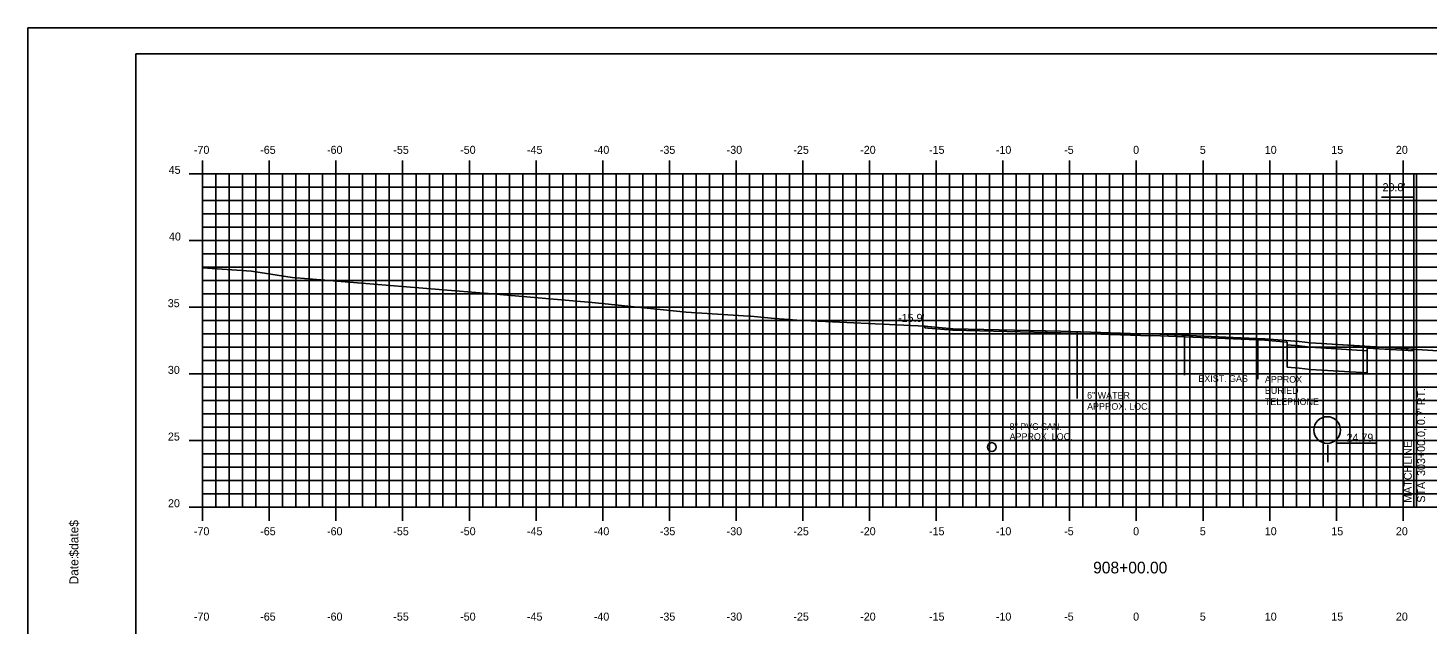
# Model space of a CAD drawing. Extents: x 1026131 to 1026301, y 394697 to 394807.
# Drawn here: x 1026131.3 to 1026236.1, y 394761.9 to 394806.5 of the extents above; entities that cross this region are included whole.
import ezdxf

# ---------------------------------------------------------------- set-up
doc = ezdxf.new("R2010")
doc.units = 0
for name, color, linetype in [('ANNOTATION', 7, 'Continuous'), ('BORDER', 7, 'Continuous'), ('D_Drainage_Culvert', 7, 'Continuous'), ('D_Drainage_Text', 7, 'Continuous'), ('D_Roadway_FinishedGrade', 7, 'Continuous'), ('D_Text_Monospaced', 7, 'Continuous'), ('D_Text_Standard', 7, 'Continuous'), ('H_V ANNOTATION', 7, 'Continuous'), ('MAJOR', 7, 'Continuous'), ('MINOR', 7, 'Continuous'), ('PLOT BOUNDARY', 7, 'Continuous'), ('S_Roadway_Centerline', 7, 'Continuous'), ('S_Utilities_UG_Gas_Line', 7, 'Continuous'), ('S_Utilities_UG_Sanitary_Sewer', 7, 'Continuous'), ('S_Utilities_UG_Water_Line', 7, 'Continuous')]:
    doc.layers.add(name, color=color, linetype=linetype)

msp = doc.modelspace()

# ---------------------------------------------------------------- linework, layer by layer
at = {"layer": 'ANNOTATION'}
for p, q in [((1026232.72, 394793.87), (1026235.14, 394793.87)), ((1026228.69, 394774), (1026228.69, 394775.3))]:
    msp.add_line(p, q, dxfattribs=at)
at = {"layer": 'BORDER'}
for p, q in [((1026299.34, 394804.61), (1026139.34, 394804.61)), ((1026139.34, 394804.61), (1026139.34, 394699.61))]:
    msp.add_line(p, q, dxfattribs=at)
at = {"layer": 'D_Drainage_Culvert'}
msp.add_circle((1026228.65, 394776.4), 1, dxfattribs=at)
at = {"layer": 'D_Drainage_Text'}
msp.add_lwpolyline([(1026229.34, 394775.42), (1026230.56, 394775.42), (1026232.4, 394775.42)], dxfattribs=at)
at = {"layer": 'D_Roadway_FinishedGrade'}
for p, q in [((1026235.14, 394770.61), (1026235.14, 394795.61)), ((1026198.48, 394784.06), (1026198.48, 394784.19)), ((1026225.65, 394781.12), (1026225.65, 394783)), ((1026231.65, 394780.68), (1026231.65, 394782.55))]:
    msp.add_line(p, q, dxfattribs=at)
for points in [[(1026198.48, 394784.19), (1026198.72, 394784.17), (1026200.58, 394784), (1026208.68, 394783.82), (1026215.4, 394783.59), (1026215.56, 394783.61), (1026221.61, 394783.35), (1026223.98, 394783.25), (1026226.55, 394783.05), (1026227.4, 394782.95), (1026235.14, 394782.46)], [(1026198.48, 394784.06), (1026198.72, 394784.05), (1026200.58, 394783.88), (1026208.68, 394783.69), (1026215.4, 394783.47), (1026215.56, 394783.49), (1026221.61, 394783.23), (1026223.98, 394783.13), (1026225.65, 394783)], [(1026225.65, 394782.79), (1026226.55, 394782.72), (1026227.4, 394782.61), (1026231.65, 394782.35)], [(1026231.65, 394782.55), (1026235.14, 394782.33)], [(1026225.65, 394781.12), (1026226.55, 394781.05), (1026227.4, 394780.95), (1026231.65, 394780.68)]]:
    msp.add_lwpolyline(points, dxfattribs=at)
at = {"layer": 'MAJOR'}
for p, q in [((1026144.34, 394796.61), (1026144.34, 394795.61)), ((1026149.34, 394796.61), (1026149.34, 394795.61)), ((1026154.34, 394796.61), (1026154.34, 394795.61)), ((1026159.34, 394796.61), (1026159.34, 394795.61)), ((1026164.34, 394796.61), (1026164.34, 394795.61)), ((1026169.34, 394796.61), (1026169.34, 394795.61)), ((1026174.34, 394796.61), (1026174.34, 394795.61)), ((1026179.34, 394796.61), (1026179.34, 394795.61)), ((1026184.34, 394796.61), (1026184.34, 394795.61)), ((1026189.34, 394796.61), (1026189.34, 394795.61)), ((1026194.34, 394796.61), (1026194.34, 394795.61)), ((1026199.34, 394796.61), (1026199.34, 394795.61)), ((1026204.34, 394796.61), (1026204.34, 394795.61)), ((1026209.34, 394796.61), (1026209.34, 394795.61)), ((1026214.34, 394796.61), (1026214.34, 394795.61)), ((1026219.34, 394796.61), (1026219.34, 394795.61)), ((1026224.34, 394796.61), (1026224.34, 394795.61)), ((1026229.34, 394796.61), (1026229.34, 394795.61)), ((1026234.34, 394796.61), (1026234.34, 394795.61)), ((1026143.34, 394795.61), (1026144.34, 394795.61)), ((1026144.34, 394795.61), (1026284.34, 394795.61)), ((1026144.34, 394770.61), (1026144.34, 394795.61)), ((1026149.34, 394770.61), (1026149.34, 394795.61)), ((1026154.34, 394770.61), (1026154.34, 394795.61)), ((1026159.34, 394770.61), (1026159.34, 394795.61)), ((1026164.34, 394770.61), (1026164.34, 394795.61)), ((1026169.34, 394770.61), (1026169.34, 394795.61)), ((1026174.34, 394770.61), (1026174.34, 394795.61)), ((1026179.34, 394770.61), (1026179.34, 394795.61)), ((1026184.34, 394770.61), (1026184.34, 394795.61)), ((1026189.34, 394770.61), (1026189.34, 394795.61)), ((1026194.34, 394770.61), (1026194.34, 394795.61)), ((1026199.34, 394770.61), (1026199.34, 394795.61)), ((1026204.34, 394770.61), (1026204.34, 394795.61)), ((1026209.34, 394770.61), (1026209.34, 394795.61)), ((1026214.34, 394770.61), (1026214.34, 394795.61)), ((1026219.34, 394770.61), (1026219.34, 394795.61)), ((1026224.34, 394770.61), (1026224.34, 394795.61)), ((1026229.34, 394770.61), (1026229.34, 394795.61)), ((1026234.34, 394770.61), (1026234.34, 394795.61)), ((1026143.34, 394790.61), (1026144.34, 394790.61)), ((1026144.34, 394790.61), (1026284.34, 394790.61)), ((1026143.34, 394785.61), (1026144.34, 394785.61)), ((1026144.34, 394785.61), (1026284.34, 394785.61)), ((1026143.34, 394780.61), (1026144.34, 394780.61)), ((1026144.34, 394780.61), (1026284.34, 394780.61)), ((1026143.34, 394775.61), (1026144.34, 394775.61)), ((1026144.34, 394775.61), (1026284.34, 394775.61)), ((1026143.34, 394770.61), (1026144.34, 394770.61)), ((1026144.34, 394770.61), (1026284.34, 394770.61)), ((1026144.34, 394769.6), (1026144.34, 394770.61)), ((1026149.34, 394769.6), (1026149.34, 394770.61)), ((1026154.34, 394769.6), (1026154.34, 394770.61)), ((1026159.34, 394769.6), (1026159.34, 394770.61)), ((1026164.34, 394769.6), (1026164.34, 394770.61)), ((1026169.34, 394769.6), (1026169.34, 394770.61)), ((1026174.34, 394769.6), (1026174.34, 394770.61)), ((1026179.34, 394769.6), (1026179.34, 394770.61)), ((1026184.34, 394769.6), (1026184.34, 394770.61)), ((1026189.34, 394769.6), (1026189.34, 394770.61)), ((1026194.34, 394769.6), (1026194.34, 394770.61)), ((1026199.34, 394769.6), (1026199.34, 394770.61)), ((1026204.34, 394769.6), (1026204.34, 394770.61)), ((1026209.34, 394769.6), (1026209.34, 394770.61)), ((1026214.34, 394769.6), (1026214.34, 394770.61)), ((1026219.34, 394769.6), (1026219.34, 394770.61)), ((1026224.34, 394769.6), (1026224.34, 394770.61)), ((1026229.34, 394769.6), (1026229.34, 394770.61)), ((1026234.34, 394769.6), (1026234.34, 394770.61))]:
    msp.add_line(p, q, dxfattribs=at)
at = {"layer": 'MINOR'}
for p, q in [((1026145.34, 394770.61), (1026145.34, 394795.61)), ((1026146.34, 394770.61), (1026146.34, 394795.61)), ((1026147.34, 394770.61), (1026147.34, 394795.61)), ((1026148.34, 394770.61), (1026148.34, 394795.61)), ((1026150.34, 394770.61), (1026150.34, 394795.61)), ((1026151.34, 394770.61), (1026151.34, 394795.61)), ((1026152.34, 394770.61), (1026152.34, 394795.61)), ((1026153.34, 394770.61), (1026153.34, 394795.61)), ((1026155.34, 394770.61), (1026155.34, 394795.61)), ((1026156.34, 394770.61), (1026156.34, 394795.61)), ((1026157.34, 394770.61), (1026157.34, 394795.61)), ((1026158.34, 394770.61), (1026158.34, 394795.61)), ((1026160.34, 394770.61), (1026160.34, 394795.61)), ((1026161.34, 394770.61), (1026161.34, 394795.61)), ((1026162.34, 394770.61), (1026162.34, 394795.61)), ((1026163.34, 394770.61), (1026163.34, 394795.61)), ((1026165.34, 394770.61), (1026165.34, 394795.61)), ((1026166.34, 394770.61), (1026166.34, 394795.61)), ((1026167.34, 394770.61), (1026167.34, 394795.61)), ((1026168.34, 394770.61), (1026168.34, 394795.61)), ((1026170.34, 394770.61), (1026170.34, 394795.61)), ((1026171.34, 394770.61), (1026171.34, 394795.61)), ((1026172.34, 394770.61), (1026172.34, 394795.61)), ((1026173.34, 394770.61), (1026173.34, 394795.61)), ((1026175.34, 394770.61), (1026175.34, 394795.61)), ((1026176.34, 394770.61), (1026176.34, 394795.61)), ((1026177.34, 394770.61), (1026177.34, 394795.61)), ((1026178.34, 394770.61), (1026178.34, 394795.61)), ((1026180.34, 394770.61), (1026180.34, 394795.61)), ((1026181.34, 394770.61), (1026181.34, 394795.61)), ((1026182.34, 394770.61), (1026182.34, 394795.61)), ((1026183.34, 394770.61), (1026183.34, 394795.61)), ((1026185.34, 394770.61), (1026185.34, 394795.61)), ((1026186.34, 394770.61), (1026186.34, 394795.61)), ((1026187.34, 394770.61), (1026187.34, 394795.61)), ((1026188.34, 394770.61), (1026188.34, 394795.61)), ((1026190.34, 394770.61), (1026190.34, 394795.61)), ((1026191.34, 394770.61), (1026191.34, 394795.61)), ((1026192.34, 394770.61), (1026192.34, 394795.61)), ((1026193.34, 394770.61), (1026193.34, 394795.61)), ((1026195.34, 394770.61), (1026195.34, 394795.61)), ((1026196.34, 394770.61), (1026196.34, 394795.61)), ((1026197.34, 394770.61), (1026197.34, 394795.61)), ((1026198.34, 394770.61), (1026198.34, 394795.61)), ((1026200.34, 394770.61), (1026200.34, 394795.61)), ((1026201.34, 394770.61), (1026201.34, 394795.61)), ((1026202.34, 394770.61), (1026202.34, 394795.61)), ((1026203.34, 394770.61), (1026203.34, 394795.61)), ((1026205.34, 394770.61), (1026205.34, 394795.61)), ((1026206.34, 394770.61), (1026206.34, 394795.61)), ((1026207.34, 394770.61), (1026207.34, 394795.61)), ((1026208.34, 394770.61), (1026208.34, 394795.61)), ((1026210.34, 394770.61), (1026210.34, 394795.61)), ((1026211.34, 394770.61), (1026211.34, 394795.61)), ((1026212.34, 394770.61), (1026212.34, 394795.61)), ((1026213.34, 394770.61), (1026213.34, 394795.61)), ((1026215.34, 394770.61), (1026215.34, 394795.61)), ((1026216.34, 394770.61), (1026216.34, 394795.61)), ((1026217.34, 394770.61), (1026217.34, 394795.61)), ((1026218.34, 394770.61), (1026218.34, 394795.61)), ((1026220.34, 394770.61), (1026220.34, 394795.61)), ((1026221.34, 394770.61), (1026221.34, 394795.61)), ((1026222.34, 394770.61), (1026222.34, 394795.61)), ((1026223.34, 394770.61), (1026223.34, 394795.61)), ((1026225.34, 394770.61), (1026225.34, 394795.61)), ((1026226.34, 394770.61), (1026226.34, 394795.61)), ((1026227.34, 394770.61), (1026227.34, 394795.61)), ((1026228.34, 394770.61), (1026228.34, 394795.61)), ((1026230.34, 394770.61), (1026230.34, 394795.61)), ((1026231.34, 394770.61), (1026231.34, 394795.61)), ((1026232.34, 394770.61), (1026232.34, 394795.61)), ((1026233.34, 394770.61), (1026233.34, 394795.61)), ((1026235.34, 394770.61), (1026235.34, 394795.61)), ((1026144.34, 394794.61), (1026284.34, 394794.61)), ((1026144.34, 394794.61), (1026145.35, 394794.61)), ((1026144.34, 394793.61), (1026284.34, 394793.61)), ((1026144.34, 394793.61), (1026145.35, 394793.61)), ((1026144.34, 394792.61), (1026284.34, 394792.61)), ((1026144.34, 394792.61), (1026145.35, 394792.61)), ((1026144.34, 394791.61), (1026284.34, 394791.61)), ((1026144.34, 394791.61), (1026145.35, 394791.61)), ((1026144.34, 394789.61), (1026284.34, 394789.61)), ((1026144.34, 394789.61), (1026145.35, 394789.61)), ((1026144.34, 394788.61), (1026284.34, 394788.61)), ((1026144.34, 394788.61), (1026145.35, 394788.61)), ((1026144.34, 394787.61), (1026284.34, 394787.61)), ((1026144.34, 394787.61), (1026145.35, 394787.61)), ((1026144.34, 394786.61), (1026284.34, 394786.61)), ((1026144.34, 394786.61), (1026145.35, 394786.61)), ((1026144.34, 394784.61), (1026284.34, 394784.61)), ((1026144.34, 394784.61), (1026145.35, 394784.61)), ((1026144.34, 394783.61), (1026284.34, 394783.61)), ((1026144.34, 394783.61), (1026145.35, 394783.61)), ((1026144.34, 394782.61), (1026284.34, 394782.61)), ((1026144.34, 394782.61), (1026145.35, 394782.61)), ((1026144.34, 394781.61), (1026284.34, 394781.61)), ((1026144.34, 394781.61), (1026145.35, 394781.61)), ((1026144.34, 394779.61), (1026284.34, 394779.61)), ((1026144.34, 394779.61), (1026145.35, 394779.61)), ((1026144.34, 394778.61), (1026284.34, 394778.61)), ((1026144.34, 394778.61), (1026145.35, 394778.61)), ((1026144.34, 394777.61), (1026284.34, 394777.61)), ((1026144.34, 394777.61), (1026145.35, 394777.61)), ((1026144.34, 394776.61), (1026284.34, 394776.61)), ((1026144.34, 394776.61), (1026145.35, 394776.61)), ((1026144.34, 394774.61), (1026284.34, 394774.61)), ((1026144.34, 394774.61), (1026145.35, 394774.61)), ((1026144.34, 394773.61), (1026284.34, 394773.61)), ((1026144.34, 394773.61), (1026145.35, 394773.61)), ((1026144.34, 394772.61), (1026284.34, 394772.61)), ((1026144.34, 394772.61), (1026145.35, 394772.61)), ((1026144.34, 394771.61), (1026284.34, 394771.61)), ((1026144.34, 394771.61), (1026145.35, 394771.61))]:
    msp.add_line(p, q, dxfattribs=at)
at = {"layer": 'PLOT BOUNDARY'}
msp.add_lwpolyline([(1026131.25, 394696.55), (1026301.25, 394696.55), (1026301.25, 394806.55), (1026131.25, 394806.55)], close=True, dxfattribs=at)
at = {"layer": 'S_Roadway_Centerline'}
msp.add_lwpolyline([(1026144.34, 394788.57), (1026148.02, 394788.31), (1026151.06, 394787.83), (1026165.76, 394786.63), (1026173.54, 394785.96), (1026180.59, 394785.25), (1026185.3, 394784.95), (1026185.43, 394784.94), (1026187.21, 394784.76), (1026187.94, 394784.71), (1026188.9, 394784.63), (1026198.51, 394784.18), (1026198.72, 394784.17), (1026200.58, 394784), (1026208.68, 394783.82), (1026215.4, 394783.59), (1026215.56, 394783.61), (1026221.61, 394783.35), (1026223.98, 394783.25), (1026226.55, 394783.05), (1026227.4, 394782.95), (1026238.96, 394782.21)], dxfattribs=at)
at = {"layer": 'S_Utilities_UG_Gas_Line'}
msp.add_line((1026217.95, 394783.51), (1026217.95, 394780.51), dxfattribs=at)
at = {"layer": 'S_Utilities_UG_Sanitary_Sewer'}
msp.add_circle((1026203.51, 394775.12), 0.333, dxfattribs=at)
at = {"layer": 'S_Utilities_UG_Water_Line'}
for p, q in [((1026209.9, 394783.77), (1026209.9, 394778.77)), ((1026223.44, 394783.28), (1026223.44, 394780.22))]:
    msp.add_line(p, q, dxfattribs=at)

# ---------------------------------------------------------------- texts
at = {"layer": 'ANNOTATION'}
msp.add_text("20.8'", height=0.6, dxfattribs=at).set_placement((1026232.8, 394794.31))
for s, p in [("STA. 303+00.0, 0.7' RT.", (1026235.99, 394770.95)), ('MATCHLINE', (1026234.99, 394770.95))]:
    msp.add_text(s, height=0.6, rotation=90, dxfattribs=at).set_placement(p)
at = {"layer": 'BORDER'}
for s, p in [('$date$', (1026135.03, 394766.91)), ('Date:', (1026135.03, 394764.82))]:
    msp.add_text(s, height=0.67, rotation=90, dxfattribs=at).set_placement(p)
at = {"layer": 'D_Drainage_Text'}
msp.add_text('24.79', height=0.6, dxfattribs=at).set_placement((1026230.1, 394775.53))
at = {"layer": 'D_Text_Monospaced'}
for s, p in [('EXIST. GAS', (1026218.99, 394780.01)), ('APPROX', (1026223.98, 394779.95)), ('BURIED ', (1026223.98, 394779.11)), ('6" WATER', (1026210.65, 394778.75)), ('TELEPHONE', (1026223.98, 394778.28)), ('APPROX. LOC.', (1026210.65, 394777.92)), ('8" PVC SAN.', (1026204.84, 394776.41)), ('APPROX. LOC.', (1026204.84, 394775.66))]:
    msp.add_text(s, height=0.5, dxfattribs=at).set_placement(p)
at = {"layer": 'D_Text_Standard'}
msp.add_text("-15.9'", height=0.6, dxfattribs=at).set_placement((1026196.48, 394784.51))
at = {"layer": 'H_V ANNOTATION'}
for s, height, p in [('-70', 0.6, (1026143.69, 394797.11)), ('-65', 0.6, (1026148.66, 394797.11)), ('-60', 0.6, (1026153.67, 394797.11)), ('-55', 0.6, (1026158.64, 394797.11)), ('-50', 0.6, (1026163.65, 394797.11)), ('-45', 0.6, (1026168.66, 394797.11)), ('-40', 0.6, (1026173.67, 394797.11)), ('-35', 0.6, (1026178.62, 394797.11)), ('-30', 0.6, (1026183.63, 394797.11)), ('-25', 0.6, (1026188.63, 394797.11)), ('-20', 0.6, (1026193.64, 394797.11)), ('-15', 0.6, (1026198.8, 394797.11)), ('-10', 0.6, (1026203.81, 394797.11)), ('-5', 0.6, (1026208.93, 394797.11)), ('0', 0.6, (1026214.1, 394797.11)), ('5', 0.6, (1026219.1, 394797.11)), ('10', 0.6, (1026223.97, 394797.11)), ('15', 0.6, (1026228.96, 394797.11)), ('20', 0.6, (1026233.8, 394797.11)), ('45', 0.6, (1026141.8, 394795.61)), ('40', 0.6, (1026141.82, 394790.61)), ('35', 0.6, (1026141.73, 394785.61)), ('30', 0.6, (1026141.74, 394780.61)), ('25', 0.6, (1026141.74, 394775.61)), ('20', 0.6, (1026141.75, 394770.61)), ('-70', 0.6, (1026143.69, 394768.51)), ('-65', 0.6, (1026148.66, 394768.51)), ('-60', 0.6, (1026153.67, 394768.51)), ('-55', 0.6, (1026158.64, 394768.51)), ('-50', 0.6, (1026163.65, 394768.51)), ('-45', 0.6, (1026168.66, 394768.51)), ('-40', 0.6, (1026173.67, 394768.51)), ('-35', 0.6, (1026178.62, 394768.51)), ('-30', 0.6, (1026183.63, 394768.51)), ('-25', 0.6, (1026188.63, 394768.51)), ('-20', 0.6, (1026193.64, 394768.51)), ('-15', 0.6, (1026198.8, 394768.51)), ('-10', 0.6, (1026203.81, 394768.51)), ('-5', 0.6, (1026208.93, 394768.51)), ('0', 0.6, (1026214.1, 394768.51)), ('5', 0.6, (1026219.1, 394768.51)), ('10', 0.6, (1026223.97, 394768.51)), ('15', 0.6, (1026228.96, 394768.51)), ('20', 0.6, (1026233.8, 394768.51)), ('908+00.00', 0.875, (1026211.1, 394765.65)), ('-70', 0.6, (1026143.69, 394762.11)), ('-65', 0.6, (1026148.66, 394762.11)), ('-60', 0.6, (1026153.67, 394762.11)), ('-55', 0.6, (1026158.64, 394762.11)), ('-50', 0.6, (1026163.65, 394762.11)), ('-45', 0.6, (1026168.66, 394762.11)), ('-40', 0.6, (1026173.67, 394762.11)), ('-35', 0.6, (1026178.62, 394762.11)), ('-30', 0.6, (1026183.63, 394762.11)), ('-25', 0.6, (1026188.63, 394762.11)), ('-20', 0.6, (1026193.64, 394762.11)), ('-15', 0.6, (1026198.8, 394762.11)), ('-10', 0.6, (1026203.81, 394762.11)), ('-5', 0.6, (1026208.93, 394762.11)), ('0', 0.6, (1026214.1, 394762.11)), ('5', 0.6, (1026219.1, 394762.11)), ('10', 0.6, (1026223.97, 394762.11)), ('15', 0.6, (1026228.96, 394762.11)), ('20', 0.6, (1026233.8, 394762.11))]:
    msp.add_text(s, height=height, dxfattribs=at).set_placement(p)
at = {"layer": 'S_Roadway_Centerline'}
for s, p in [('C', (1026215.55, 394783.61)), ('L', (1026215.56, 394783.61))]:
    msp.add_text(s, height=0.0146, dxfattribs=at).set_placement(p)

doc.saveas('drawing.dxf')
